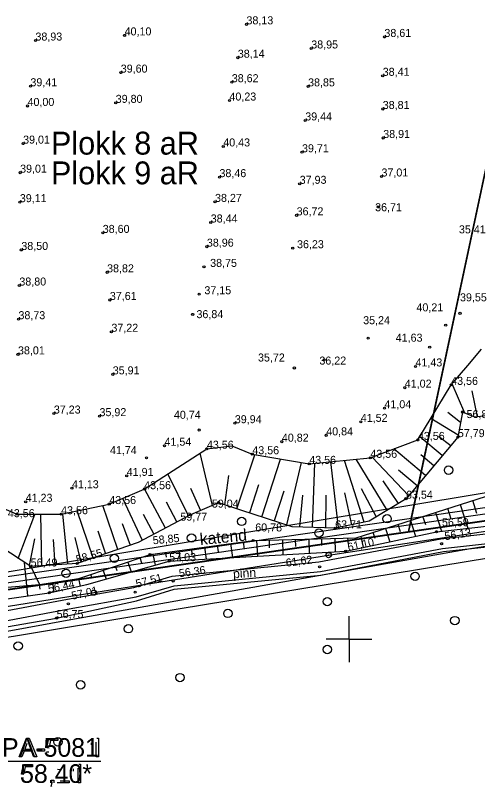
# Model space of a CAD drawing. Extents: x 700746 to 706058, y 6570320 to 6580460.
# Drawn here: x 702897.9 to 703039.3, y 6575454.9 to 6575690.9 of the extents above; entities that cross this region are included whole.
import ezdxf

# ---------------------------------------------------------------- set-up
doc = ezdxf.new("R2010")
doc.units = 0
for name, color, linetype in [('GEOLPUNKT', 7, 'Continuous'), ('HALJASTUS', 7, 'Continuous'), ('illumineerimisjooned', 7, 'Continuous'), ('Kaitsevöönd', 7, 'Continuous'), ('kataster', 7, 'Continuous'), ('KORGUS-EH2000', 7, 'Continuous'), ('KPKAABEL', 7, 'Continuous'), ('Plokid', 7, 'Continuous'), ('POST', 7, 'Continuous'), ('RELJEEF', 7, 'Continuous'), ('TEE', 7, 'Continuous'), ('Tmaad_maeeraldised_kehtivad', 7, 'Continuous'), ('VEEKOGU', 7, 'Continuous'), ('VORK', 7, 'Continuous'), ('VWX2_MV_PLOKK', 7, 'Continuous')]:
    doc.layers.add(name, color=color, linetype=linetype)

msp = doc.modelspace()

# ---------------------------------------------------------------- linework, layer by layer
at = {"layer": 'GEOLPUNKT'}
msp.add_line((702893.11, 6575462.61), (702924.02, 6575462.61), dxfattribs=at)
msp.add_line((702893.11, 6575462.61), (702924.02, 6575462.61), dxfattribs=at)
for points in [[(702899.08, 6575464), (702901.27, 6575469.7), (702902.09, 6575469.7), (702904.42, 6575464), (702903.56, 6575464), (702902.9, 6575465.73), (702900.51, 6575465.73), (702899.88, 6575464), (702899.08, 6575464)], [(702908.17, 6575466.61), (702907.51, 6575466.7), (702908.06, 6575469.63), (702910.89, 6575469.63), (702910.89, 6575468.96), (702908.62, 6575468.96), (702908.31, 6575467.43)], [(702922.85, 6575469.73), (702923.3, 6575469.73), (702923.3, 6575464)], [(702901.35, 6575468.02), (702900.72, 6575466.34)], [(702900.72, 6575466.34), (702902.66, 6575466.34), (702902.06, 6575467.92)], [(702921.2, 6575467.62), (702921.2, 6575468.3)], [(702923.3, 6575464), (702922.6, 6575464), (702922.6, 6575468.46)], [(702904.65, 6575465.72), (702904.65, 6575466.42), (702906.81, 6575466.42), (702906.81, 6575465.72), (702904.65, 6575465.72)], [(702907.38, 6575465.5), (702908.12, 6575465.56)], [(702900.42, 6575458.61), (702899.77, 6575458.7), (702900.32, 6575461.63), (702903.15, 6575461.63), (702903.15, 6575460.96), (702900.88, 6575460.96), (702900.57, 6575459.43)], [(702911.47, 6575460.01), (702910.74, 6575460.08)], [(702915.67, 6575459.62), (702915.67, 6575460.3)], [(702917.77, 6575456), (702917.07, 6575456), (702917.07, 6575460.46)], [(702917.31, 6575461.73), (702917.77, 6575461.73), (702917.77, 6575456)], [(702899.64, 6575457.5), (702900.37, 6575457.56)], [(702909.02, 6575454.87), (702908.82, 6575455.17)], [(702908.87, 6575456), (702908.87, 6575456.8), (702909.67, 6575456.8), (702909.67, 6575456)], [(702909.27, 6575456), (702908.87, 6575456)], [(702914.38, 6575456.68), (702914.38, 6575456), (702910.61, 6575456)], [(702911.59, 6575456.68), (702914.38, 6575456.68)]]:
    msp.add_lwpolyline(points, dxfattribs=at)
at = {"layer": 'HALJASTUS'}
msp.add_line((702902.55, 6575522.25), (702905.24, 6575516.78), dxfattribs=at)
msp.add_lwpolyline([(702868.07, 6575485.72), (702866.82, 6575498.83), (702910.5, 6575506.46), (702934.94, 6575511.72), (702946.5, 6575515.31), (702991.31, 6575519.57), (703028.9, 6575526.86), (703057.45, 6575529.86), (703073.09, 6575531.97), (703122.4, 6575538.74), (703175.48, 6575547.5), (703217.62, 6575554.37), (703241.81, 6575557.45), (703262.67, 6575561.84), (703280.4, 6575573.6), (703298.96, 6575585.05), (703313, 6575594.45), (703326.63, 6575610.36)], dxfattribs=at)
for centre in [(703030.46, 6575551.74), (703011.64, 6575536.85), (702967.12, 6575536.03), (702990.77, 6575532.51), (702951.78, 6575530.97), (702928.15, 6575524.75), (702913.39, 6575520.15), (703020.2, 6575519.24), (702993.36, 6575511.49), (702962.92, 6575507.89), (703032.37, 6575505.68), (702932.48, 6575503.18), (702898.72, 6575497.92), (702993.36, 6575496.84), (702948.25, 6575488.23), (702917.81, 6575486.02), (702910.89, 6575468.57)]:
    msp.add_circle(centre, 1.28, dxfattribs=at)
at = {"layer": 'illumineerimisjooned'}
msp.add_lwpolyline([(703275.45, 6577071.68), (703358.03, 6576531.93), (703309.57, 6576228.79), (703291.69, 6575965.8), (703292.02, 6575933.77), (703296.8, 6575575.06), (702854, 6575511.22), (702839.23, 6575620.77), (702850.34, 6575977.31), (702784.78, 6576064.06), (702784.62, 6576095.83), (702844.43, 6576209.85), (702855.46, 6576267.3), (702846.53, 6576489.41), (702878.89, 6576547.09), (702976.89, 6576643.26), (702915.33, 6577059.56)], dxfattribs=at)
at = {"layer": 'Kaitsevöönd'}
for points in [[(703404.08, 6576352.03), (703454.73, 6576005.46), (703455.39, 6576000.16), (703516.46, 6575600.64), (703378.76, 6575580.78), (703360.22, 6575577.3), (703249.34, 6575561.08), (703243.21, 6575560.09), (703037.16, 6575527.65), (702916.01, 6575506.13), (702857.92, 6575495.54), (702854.94, 6575495.05), (702852.29, 6575508.95), (702831.77, 6575505.31), (702827.8, 6575504.98), (702697.05, 6575486.77), (702630.85, 6575867.26), (702597.75, 6576057.43)], [(703057.55, 6575527.21), (702948.27, 6575509.25), (702866.4, 6575495.73), (702861.96, 6575495.44), (702858.68, 6575497.18), (702855.69, 6575499.88), (702853.95, 6575503.84), (702843.23, 6575549.52), (702845.07, 6575698.17), (702845.65, 6575745.88), (702846.42, 6575800.35), (702847.19, 6575873.76), (702847.19, 6575901.67), (702846.52, 6575932.87), (702845.54, 6575980.61), (702820.94, 6576032.47), (702787.75, 6576109.14)], [(702808.74, 6576109.92), (702830.03, 6576060.94), (702864.5, 6575987.24), (702865.48, 6575983.2), (702867.41, 6575887.93), (702864.44, 6575639.03), (702863.5, 6575550.31), (702871.75, 6575516.76), (703096.25, 6575553.86)]]:
    msp.add_lwpolyline(points, dxfattribs=at)
at = {"layer": 'kataster'}
msp.add_lwpolyline([(702852.27, 6575508.89), (702837.26, 6575620.73), (702848.38, 6575976.59), (702782.85, 6576063.35), (702782.57, 6576096.37), (702842.53, 6576210.56), (702853.4, 6576267.5), (702844.46, 6576489.93), (702877.29, 6576548.25), (702974.72, 6576643.9), (702913.57, 6577058.07), (702784.04, 6577102.84), (702746.48, 6577248.7), (702719.69, 6577297.36), (702713.81, 6577334.91), (703089.87, 6577211.79), (703231.53, 6577106.55), (703277.36, 6577072.83), (703360.09, 6576531.99), (703311.6, 6576228.52), (703293.62, 6575965.66), (703298.84, 6575573.29)], close=True, dxfattribs=at)
msp.add_lwpolyline([(702782.57, 6576096.37), (702782.85, 6576063.35), (702848.38, 6575976.59), (702837.26, 6575620.73), (702852.27, 6575508.89), (703298.84, 6575573.29), (703375.63, 6575584.41), (703375.41, 6575624), (703375.74, 6575634.8), (703375.62, 6575689.75), (703370.21, 6575799.42), (703370.29, 6575828.47), (703365.86, 6576033.99), (703361.97, 6576073.22), (703340.19, 6576155.31)], dxfattribs=at)
at = {"layer": 'KORGUS-EH2000'}
for centre in [(702968.6, 6575688.22), (702931.3, 6575684.83), (703010.82, 6575684.36), (702904.01, 6575683.25), (702988.43, 6575680.83), (702965.95, 6575678.01), (702930.12, 6575673.44), (703010.3, 6575672.46), (702964.1, 6575670.5), (702902.47, 6575669.26), (702987.46, 6575669.22), (702963.39, 6575664.89), (702901.59, 6575663.23), (702928.58, 6575664.18), (703010.31, 6575662.31), (702986.59, 6575658.8), (703010.46, 6575653.43), (702900.24, 6575651.7), (702961.5, 6575650.84), (702985.6, 6575649.06), (702899.32, 6575642.81), (702960.33, 6575641.44), (703009.92, 6575641.64), (702984.89, 6575639.4), (702899.23, 6575633.78), (702958.98, 6575633.86), (703008.92, 6575632.32), (702983.95, 6575629.75), (702957.66, 6575627.56), (702924.61, 6575624.37), (702956.49, 6575620.16), (702899.69, 6575619.15), (702982.76, 6575619.68), (702955.6, 6575613.96), (702925.94, 6575612.3), (702899.09, 6575608.26), (702926.79, 6575603.84), (702954.12, 6575605.59), (702952.14, 6575599.42), (703033.96, 6575599.76), (702898.81, 6575597.95), (702927.26, 6575594.11), (703029.58, 6575596.1), (703005.83, 6575592.17), (703024.68, 6575589.39), (702898.67, 6575587.18), (702992.39, 6575585.53), (702983.25, 6575583.02), (703020.33, 6575583.49), (702927.67, 6575581.07), (703031.26, 6575577.84), (703017.05, 6575577), (703010.83, 6575570.69), (702909.64, 6575569.07), (702923.62, 6575568.27), (703034.71, 6575569.53), (702965.03, 6575566.11), (703003.59, 6575566.53), (702954.13, 6575564.02), (702993.01, 6575562.39), (703021.07, 6575560.99), (703033.3, 6575561.86), (702943.51, 6575559.22), (702979.43, 6575560.46), (702956.49, 6575558.3), (702970.39, 6575556.61), (702938, 6575555.49), (703006.51, 6575555.52), (702987.82, 6575553.66), (702931.95, 6575549.98), (702915.18, 6575546.2), (702937.42, 6575545.99), (702901.02, 6575542.06), (703017.43, 6575543), (702926.61, 6575541.36), (702960.06, 6575541.78), (702898.31, 6575538.25), (702911.87, 6575538.25), (702951.5, 6575538.06), (702995.75, 6575533.94), (703026.77, 6575532.89), (702970.64, 6575530.23), (703028.33, 6575529.22), (702939.09, 6575525.89), (702998.98, 6575526.95), (702916.81, 6575523.18), (702944.96, 6575523.88), (702902.55, 6575522.25), (702991, 6575522.15), (702946.19, 6575517.81), (702908.2, 6575514.19), (702934.51, 6575514.37), (702914.09, 6575510.79), (702910.5, 6575506.46)]:
    msp.add_circle(centre, 0.32, dxfattribs=at)
at = {"layer": 'KPKAABEL'}
msp.add_lwpolyline([(702819.63, 6576245.48), (702836.59, 6576184.26), (702797.6, 6576109.54), (702828.99, 6576046.16), (702858.93, 6575984.92), (702857.42, 6575888.76), (702856.51, 6575810.46), (702856.12, 6575711.01), (702855.37, 6575615.97), (702854.39, 6575550.18), (702865.02, 6575505.16), (702921.92, 6575514.25), (702993.74, 6575525.72), (703056.42, 6575535.34), (703120.25, 6575545.36), (703173.19, 6575553.73), (703215.56, 6575560.47), (703265.05, 6575567.87), (703307.33, 6575597.7), (703332.6, 6575614.36)], dxfattribs=at)
at = {"layer": 'Plokid'}
for points in [[(703290.64, 6576959.22), (703356.01, 6576531.94), (703307.59, 6576229.01), (703289.69, 6575965.85), (703290.02, 6575933.75), (703291.51, 6575829.64), (703294.32, 6575609.52), (703294.77, 6575576.79), (703154.76, 6575556.6), (703019.06, 6575536.97), (703053.36, 6575698.14), (703145.59, 6575981.92), (703123.04, 6576234.88), (703120.61, 6576749.6), (703011.59, 6576989.47), (702968.34, 6577084.63), (702917.3, 6577059.88)], [(702917.13, 6577061.05), (702979.02, 6576642.55), (702880.49, 6576545.86), (702848.55, 6576488.92), (702857.46, 6576267.15), (702846.34, 6576209.18), (702786.62, 6576095.35), (702786.77, 6576064.74), (702852.36, 6575977.95), (702841.24, 6575620.87), (702855.72, 6575513.48), (703019.07, 6575537.04)]]:
    msp.add_lwpolyline(points, dxfattribs=at)
at = {"layer": 'POST'}
for centre, radius in [((702993.74, 6575525.72), 0.8), ((702993.74, 6575525.72), 0.0747), ((702921.92, 6575514.25), 0.8), ((702921.92, 6575514.25), 0.0747)]:
    msp.add_circle(centre, radius, dxfattribs=at)
at = {"layer": 'RELJEEF'}
for p, q in [((703035.45, 6575569.23), (703031.51, 6575578.14)), ((703037.57, 6575575.98), (703039.2, 6575568.05)), ((703030.24, 6575569.47), (703034.13, 6575566.38)), ((703033.4, 6575562.45), (703025.03, 6575567.57)), ((703028.53, 6575556.2), (703021.67, 6575561.97)), ((703027.34, 6575562.19), (703031.11, 6575559.26)), ((702958.18, 6575540.96), (702954.41, 6575556.95)), ((703023.38, 6575550.07), (703013.7, 6575558.22)), ((702965.7, 6575539.89), (702971.2, 6575556.48)), ((702973.31, 6575537.42), (702979.03, 6575555.15)), ((702996.81, 6575534.16), (702994.39, 6575554.32)), ((703004.63, 6575535.82), (702998.56, 6575554.73)), ((703011.66, 6575539.49), (703002.15, 6575555.09)), ((703018.23, 6575543.95), (703007.06, 6575555.72)), ((703021.97, 6575556.49), (703025.96, 6575553.14)), ((702980.92, 6575534.96), (702985.48, 6575554.06)), ((702988.83, 6575534.19), (702989.56, 6575553.84)), ((703015.1, 6575551.81), (703020.81, 6575547.01)), ((702950.87, 6575537.73), (702944.56, 6575550.6)), ((702963.13, 6575550.14), (702961.91, 6575541.16)), ((702972.29, 6575547.23), (702969.5, 6575538.65)), ((703010.36, 6575548.5), (703015.08, 6575541.57)), ((702943.8, 6575533.98), (702937.42, 6575545.99)), ((702951.47, 6575546.23), (702954.51, 6575539.37)), ((702980.07, 6575545.33), (702977.11, 6575536.19)), ((702998.64, 6575544.76), (703000.72, 6575534.99)), ((703003.72, 6575546.1), (703008.25, 6575537.4)), ((702936.73, 6575530.23), (702930.72, 6575543.11)), ((702985.78, 6575544.1), (702984.84, 6575534.34)), ((702992.87, 6575544.11), (702992.83, 6575534.05)), ((703039.14, 6575538.42), (703037.86, 6575542.41)), ((702929.25, 6575527.43), (702924.63, 6575540.95)), ((702944.06, 6575542.01), (702947.33, 6575535.85)), ((703031.27, 6575536.75), (703030.24, 6575539.98)), ((703034.05, 6575541.2), (703036.35, 6575533.98)), ((702898.73, 6575524.74), (702903.86, 6575538.19)), ((702905.98, 6575522.47), (702905.64, 6575538.25)), ((702913.96, 6575522.99), (702912.38, 6575538.35)), ((702921.68, 6575524.85), (702916.75, 6575539.28)), ((702937, 6575538.25), (702940.27, 6575532.1)), ((703026.43, 6575538.77), (703028.25, 6575533.06)), ((702930.56, 6575535.36), (702933.04, 6575528.73)), ((703018.81, 6575536.34), (703020.35, 6575531.52)), ((703023.45, 6575534.96), (703022.62, 6575537.56)), ((702923.08, 6575533.13), (702925.47, 6575526.14)), ((703011.19, 6575533.91), (703012.48, 6575529.84)), ((703015.71, 6575532.9), (703015, 6575535.13)), ((702903.74, 6575530.68), (702902.08, 6575522.56)), ((702916.08, 6575531.15), (702917.9, 6575523.55)), ((702983.7, 6575528.33), (702983.64, 6575530.56)), ((702987.64, 6575530.67), (702987.75, 6575526.32)), ((702991.69, 6575528.66), (702991.64, 6575530.77)), ((702995.63, 6575530.87), (702995.74, 6575526.77)), ((702999.78, 6575529.07), (702999.63, 6575530.98)), ((703003.56, 6575531.48), (703004.32, 6575528.09)), ((703007.96, 6575530.85), (703007.37, 6575532.7)), ((702909.47, 6575530.49), (702909.97, 6575522.73)), ((702955.78, 6575528.18), (702956.29, 6575524.53)), ((702960.02, 6575526.74), (702959.75, 6575528.73)), ((702963.71, 6575529.28), (702964.3, 6575524.98)), ((702967.96, 6575527.51), (702967.67, 6575529.82)), ((702971.64, 6575530.25), (702971.97, 6575525.42)), ((702975.7, 6575528), (702975.64, 6575530.36)), ((702979.64, 6575530.46), (702979.76, 6575525.86)), ((702939.93, 6575526), (702940.65, 6575522.66)), ((702944.09, 6575525.12), (702943.9, 6575526.55)), ((702947.86, 6575527.09), (702948.27, 6575524.07)), ((702952.05, 6575525.97), (702951.82, 6575527.64)), ((702932.31, 6575523.61), (702933.34, 6575520.57)), ((702936.61, 6575523.27), (702936.1, 6575524.88)), ((702929, 6575520.9), (702928.52, 6575522.33)), ((702921.36, 6575518.53), (702920.94, 6575519.79)), ((702924.73, 6575521.06), (702925.63, 6575518.37)), ((702905.44, 6575515.3), (702905.27, 6575516.78)), ((702909.23, 6575517.37), (702909.65, 6575514.5)), ((702913.38, 6575516.65), (702913.18, 6575517.95)), ((702917.14, 6575518.54), (702917.68, 6575516.24))]:
    msp.add_line(p, q, dxfattribs=at)
for points in [[(703109.83, 6575576.41), (703038.52, 6575567.97), (703034.71, 6575569.53), (703033.3, 6575561.86), (703017.43, 6575543), (703006.2, 6575536.16), (702995.75, 6575533.94), (702982.57, 6575534.43), (702966.91, 6575539.48), (702960.06, 6575541.78), (702951.5, 6575538.06), (702935.48, 6575529.56), (702916.81, 6575523.18), (702902.55, 6575522.25), (702893.39, 6575528.22)], [(702852.59, 6575506.08), (702885.25, 6575510.89), (702908.2, 6575514.19), (702919.76, 6575516.69), (702944.96, 6575523.88), (702998.98, 6575526.95), (703026.77, 6575532.89), (703071.81, 6575537.99), (703090.51, 6575541.68), (703101.16, 6575547.83), (703155.9, 6575557.31), (703193.39, 6575562.08), (703196.05, 6575566.19)], [(702853.89, 6575509.3), (702881.9, 6575514.82), (702905.24, 6575516.78), (702917.28, 6575518.56), (702939.09, 6575525.89), (702970.64, 6575530.23), (703002.17, 6575531.04), (703051.61, 6575546.79), (703090.96, 6575551.75), (703094.14, 6575554.91), (703156.15, 6575560.02), (703189.36, 6575564.99), (703196.05, 6575566.19)], [(702900.61, 6575523.35), (702901.28, 6575516.44), (702901.55, 6575513.23)]]:
    msp.add_lwpolyline(points, dxfattribs=at)
at = {"layer": 'TEE'}
for points in [[(702866.68, 6575500.3), (702865.33, 6575503.17), (702913.84, 6575512.27), (702934.16, 6575515.83), (702945.9, 6575519.28), (702990.79, 6575523.64), (703028.1, 6575530.7), (703056.59, 6575533.88), (703072.7, 6575535.72), (703121.62, 6575542.84), (703174.75, 6575551.03), (703216.96, 6575558.17), (703240.91, 6575561.7), (703261.23, 6575565.45), (703277.33, 6575576.54), (703296.65, 6575588.32), (703310.1, 6575597.26), (703323.05, 6575612.04)], [(702866.68, 6575500.3), (702914.35, 6575509.31), (702934.85, 6575512.91), (702946.47, 6575516.33), (702991.21, 6575520.67), (703028.56, 6575527.74), (703056.93, 6575530.91), (703073.08, 6575532.75), (703122.06, 6575539.87), (703175.22, 6575548.07), (703217.43, 6575555.21), (703241.4, 6575558.74), (703262.39, 6575562.62), (703278.96, 6575574.02), (703298.25, 6575585.79), (703312.1, 6575594.98), (703325.32, 6575610.08)]]:
    msp.add_lwpolyline(points, dxfattribs=at)
at = {"layer": 'Tmaad_maeeraldised_kehtivad'}
msp.add_lwpolyline([(703277.3, 6577072.8), (703360.06, 6576531.93), (703311.56, 6576228.56), (703293.69, 6575965.74), (703294.02, 6575933.8), (703298.82, 6575573.33), (702852.29, 6575508.95), (702837.23, 6575620.66), (702848.32, 6575976.66), (702782.78, 6576063.39), (702782.61, 6576096.32), (702842.53, 6576210.52), (702853.45, 6576267.45), (702844.51, 6576489.89), (702877.28, 6576548.31), (702974.76, 6576643.97), (702913.53, 6577058.07)], dxfattribs=at)
at = {"layer": 'VEEKOGU'}
msp.add_lwpolyline([(702885.85, 6575543.72), (702898.31, 6575538.25), (702911.87, 6575538.25), (702926.61, 6575541.36), (702937.3, 6575545.91), (702956.49, 6575558.3), (702964.07, 6575559.22), (702970.39, 6575556.61), (702987.82, 6575553.66), (703006.51, 6575555.52), (703021.07, 6575560.99), (703031.26, 6575577.84), (703036.32, 6575583.79), (703040.53, 6575588.75)], dxfattribs=at)
msp.add_lwpolyline([(702885.85, 6575543.72), (702898.31, 6575538.25), (702911.87, 6575538.25), (702926.61, 6575541.36), (702937.3, 6575545.91), (702956.49, 6575558.3), (702964.07, 6575559.22), (702970.39, 6575556.61), (702987.82, 6575553.66), (703006.51, 6575555.52), (703021.07, 6575560.99), (703031.26, 6575577.84), (703036.32, 6575583.79), (703040.53, 6575588.75)], dxfattribs=at)
at = {"layer": 'VORK'}
for q in [(703000, 6575507), (703000, 6575507), (702993, 6575500), (702993, 6575500), (703007, 6575500), (703000, 6575493), (703007, 6575500), (703000, 6575493)]:
    msp.add_line((703000, 6575500), q, dxfattribs=at)
at = {"layer": 'VWX2_MV_PLOKK'}
msp.add_lwpolyline([(703187.67, 6576999.67), (703190.39, 6576656.32), (703340.88, 6576657.54), (703360.09, 6576531.99), (703311.6, 6576228.52), (703293.62, 6575965.66), (703294.04, 6575933.77), (703295.43, 6575829.7), (703298.36, 6575609.6), (703298.84, 6575573.29), (703155.29, 6575552.59), (703018.17, 6575532.81), (703053.36, 6575698.14), (703145.59, 6575981.92), (703123.04, 6576234.88), (703120.61, 6576749.6), (703011.59, 6576989.47)], dxfattribs=at)
msp.add_lwpolyline([(703187.67, 6576999.67), (703190.39, 6576656.32), (703340.88, 6576657.54), (703360.09, 6576531.99), (703311.6, 6576228.52), (703293.62, 6575965.66), (703294.04, 6575933.77), (703295.43, 6575829.7), (703298.36, 6575609.6), (703298.84, 6575573.29), (703155.29, 6575552.59), (703018.17, 6575532.81), (703053.36, 6575698.14), (703145.59, 6575981.92), (703123.04, 6576234.88), (703120.61, 6576749.6), (703011.59, 6576989.47)], dxfattribs=at)
msp.add_lwpolyline([(703145.59, 6575981.92), (703053.36, 6575698.14), (703018.17, 6575532.81), (702852.27, 6575508.89), (702837.26, 6575620.73), (702848.38, 6575976.59), (702782.85, 6576063.35), (702782.57, 6576096.37), (702842.53, 6576210.56), (702853.4, 6576267.5), (702842.72, 6576158.42), (702865.95, 6575985.44), (702867.94, 6575888.34), (702866.03, 6575711.28), (702981.97, 6575701.33), (703059.38, 6575886.59), (703051.03, 6576091.21), (703067.36, 6576229.67), (703076.01, 6576303.02), (703101.31, 6576579.97), (703072.3, 6576854.63), (703072.13, 6576856.26), (703120.61, 6576749.6), (703123.04, 6576234.88)], close=True, dxfattribs=at)
msp.add_lwpolyline([(703145.59, 6575981.92), (703053.36, 6575698.14), (703018.17, 6575532.81), (702852.27, 6575508.89), (702837.26, 6575620.73), (702848.38, 6575976.59), (702782.85, 6576063.35), (702782.57, 6576096.37), (702842.53, 6576210.56), (702853.4, 6576267.5), (702842.72, 6576158.42), (702865.95, 6575985.44), (702867.94, 6575888.34), (702866.03, 6575711.28), (702981.97, 6575701.33), (703059.38, 6575886.59), (703051.03, 6576091.21), (703067.36, 6576229.67), (703076.01, 6576303.02), (703101.31, 6576579.97), (703072.3, 6576854.63), (703072.13, 6576856.26), (703120.61, 6576749.6), (703123.04, 6576234.88)], close=True, dxfattribs=at)

# ---------------------------------------------------------------- texts
at = {"layer": 'GEOLPUNKT'}
for s, p in [('PA-5081', (702893.78, 6575464)), ('58,40*', (702899.31, 6575456))]:
    msp.add_text(s, height=5.7, dxfattribs=at).set_placement(p)
at = {"layer": 'KORGUS-EH2000'}
for s, p in [('38,13 ', (702968.6, 6575688.22)), ('40,10 ', (702931.3, 6575684.83)), ('38,61 ', (703010.82, 6575684.36)), ('38,93 ', (702904.01, 6575683.25)), ('38,95 ', (702988.43, 6575680.83)), ('38,14 ', (702965.95, 6575678.01)), ('39,60 ', (702930.12, 6575673.44)), ('38,41 ', (703010.3, 6575672.46)), ('38,62 ', (702964.1, 6575670.5)), ('39,41 ', (702902.47, 6575669.26)), ('38,85 ', (702987.46, 6575669.22)), ('40,00 ', (702901.59, 6575663.23)), ('39,80 ', (702928.58, 6575664.18)), ('40,23 ', (702963.39, 6575664.89)), ('38,81 ', (703010.31, 6575662.31)), ('39,44 ', (702986.59, 6575658.8)), ('38,91 ', (703010.46, 6575653.43)), ('39,01 ', (702900.24, 6575651.7)), ('40,43 ', (702961.5, 6575650.84)), ('39,71 ', (702985.6, 6575649.06)), ('39,01 ', (702899.32, 6575642.81)), ('38,46 ', (702960.33, 6575641.44)), ('37,01 ', (703009.92, 6575641.64)), ('37,93 ', (702984.89, 6575639.4)), ('39,11 ', (702899.23, 6575633.78)), ('38,27 ', (702958.98, 6575633.86)), ('36,72 ', (702983.95, 6575629.75)), ('36,71 ', (703007.98, 6575631)), ('38,44 ', (702957.66, 6575627.56)), ('38,60 ', (702924.61, 6575624.37)), ('35,41 ', (703033.63, 6575624.23)), ('38,96 ', (702956.49, 6575620.16)), ('38,50 ', (702899.69, 6575619.15)), ('36,23 ', (702984.08, 6575619.68)), ('38,75 ', (702957.49, 6575613.96)), ('38,82 ', (702925.94, 6575612.3)), ('38,80 ', (702899.09, 6575608.26)), ('37,61 ', (702926.79, 6575603.84)), ('37,15 ', (702955.73, 6575605.59)), ('39,55 ', (703033.96, 6575603.43)), ('40,21 ', (703020.62, 6575600.35)), ('38,73 ', (702898.81, 6575597.95)), ('36,84 ', (702953.29, 6575598.27)), ('35,24 ', (703004.32, 6575596.42)), ('37,22 ', (702927.26, 6575594.11)), ('41,63 ', (703014.28, 6575591.07)), ('38,01 ', (702898.67, 6575587.18)), ('35,72 ', (702972.13, 6575585)), ('36,22 ', (702990.92, 6575584.06)), ('41,43 ', (703020.33, 6575583.49)), ('35,91 ', (702927.67, 6575581.07)), ('43,56 ', (703031.26, 6575577.84)), ('41,02 ', (703017.05, 6575577)), ('41,04 ', (703010.83, 6575570.69)), ('37,23 ', (702909.64, 6575569.07)), ('35,92 ', (702923.62, 6575568.27)), ('40,74 ', (702946.39, 6575567.47)), ('39,94 ', (702965.03, 6575566.11)), ('41,52 ', (703003.59, 6575566.53)), ('56,85 ', (703035.97, 6575567.68)), ('40,84 ', (702993.01, 6575562.39)), ('57,79 ', (703033.3, 6575561.86)), ('41,54 ', (702943.51, 6575559.22)), ('40,82 ', (702979.43, 6575560.46)), ('43,56 ', (703021.07, 6575560.99)), ('41,74 ', (702926.81, 6575556.64)), ('43,56 ', (702956.49, 6575558.3)), ('43,56 ', (702970.39, 6575556.61)), ('43,56 ', (703006.51, 6575555.52)), ('43,56 ', (702987.82, 6575553.66)), ('41,91 ', (702931.95, 6575549.98)), ('41,13 ', (702915.18, 6575546.2)), ('43,56 ', (702937.3, 6575545.91)), ('63,54 ', (703017.43, 6575543)), ('41,23 ', (702901.02, 6575542.06)), ('43,56 ', (702926.61, 6575541.36)), ('59,04 ', (702958.01, 6575540.27)), ('43,56 ', (702911.87, 6575538.25)), ('43,56 ', (702895.57, 6575537.35)), ('59,77 ', (702948.38, 6575536.27)), ('60,78 ', (702971.29, 6575532.98)), ('63,71 ', (702995.75, 6575533.94)), ('56,59 ', (703028.44, 6575534.57)), ('57,03 ', (702944.96, 6575523.88)), ('56,49 ', (702902.55, 6575522.25)), ('56,75 ', (702910.5, 6575506.46))]:
    msp.add_text(s, height=2.45, dxfattribs=at).set_placement(p)
for s, rotation, p in [('56,13 ', 8.9378, (703029.42, 6575530.28)), ('58,85 ', 5.3311, (702940.03, 6575529.03)), ('61,10 ', 12.3199, (702999.83, 6575526.93)), ('58,55 ', 15.5278, (702916.81, 6575523.18)), ('61,62 ', 7.3342, (702980.79, 6575522.15)), ('56,36 ', 7.8815, (702948.1, 6575518.93)), ('57,51 ', 14.5561, (702935.06, 6575515.74)), ('56,44 ', 11.792, (702908.14, 6575514.17)), ('57,01 ', 12.6457, (702915.32, 6575512.06))]:
    msp.add_text(s, height=2.45, rotation=rotation, dxfattribs=at).set_placement(p)
at = {"layer": 'Plokid'}
for s, p in [('Plokk 8 aR', (702908.77, 6575648.34)), ('Plokk 9 aR', (702908.77, 6575639.24))]:
    msp.add_text(s, height=7, dxfattribs=at).set_placement(p)
at = {"layer": 'RELJEEF'}
msp.add_text('katend', height=3.6, rotation=5.4509, dxfattribs=at).set_placement((702954.48, 6575528.81))
at = {"layer": 'TEE'}
msp.add_text('pinn', height=2.8, rotation=3.2993, dxfattribs=at).set_placement((702964.56, 6575518.64))

doc.saveas('drawing.dxf')
